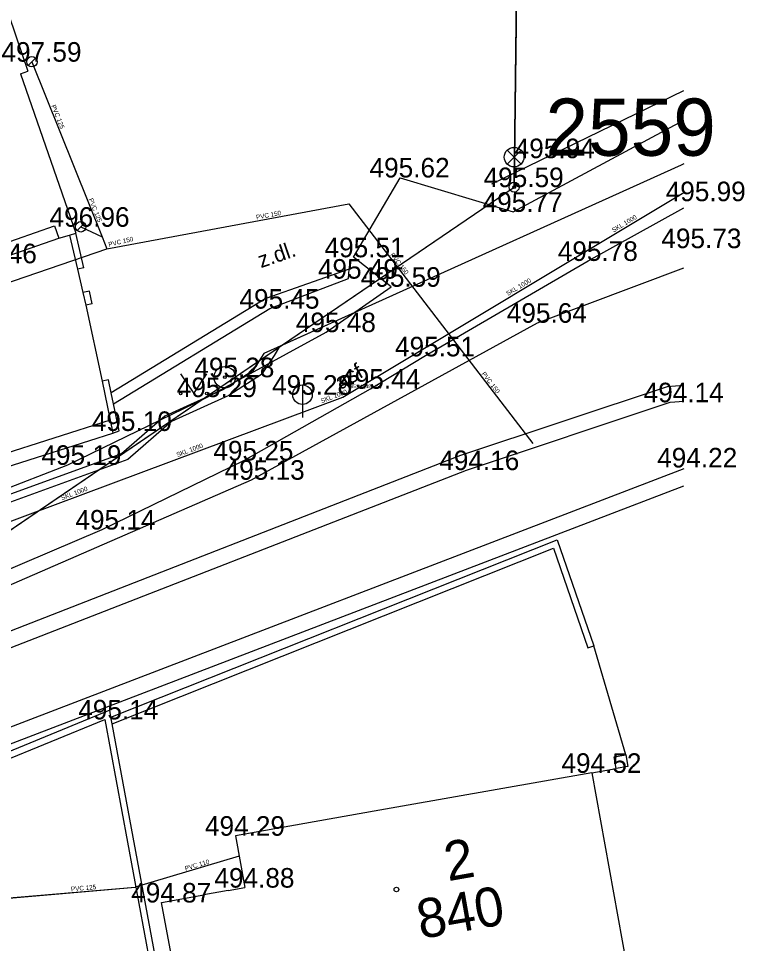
# Model space of a CAD drawing. Extents: x -669642 to -669119, y -1131006 to -1130466.
# Drawn here: x -669215.58 to -669187.76, y -1130590.75 to -1130555.28 of the extents above; entities that cross this region are included whole.
import ezdxf

# ---------------------------------------------------------------- set-up
doc = ezdxf.new("R2010")
doc.units = 0
for name, color, linetype in [('G_Bod_tecka', 7, 'Continuous'), ('G_Bod_vyska', 7, 'Continuous'), ('G_Bodove_pole', 7, 'Continuous'), ('G_Budovy-znacky', 7, 'Continuous'), ('G_Budovy_Objekty', 7, 'Continuous'), ('G_Budovy_vstupy', 7, 'Continuous'), ('G_Cesty_Schody', 7, 'Continuous'), ('G_Cisla_orientacni', 7, 'Continuous'), ('G_Cisla_popisna', 7, 'Continuous'), ('G_Objekty_technicke', 7, 'Continuous'), ('G_Plochy_zpevnene', 7, 'Continuous'), ('G_Ploty', 7, 'Continuous'), ('G_Ploty_vstupy', 7, 'Continuous'), ('G_Popisy_povrchu', 7, 'Continuous'), ('G_Site-kanalizace', 7, 'Continuous'), ('G_Z_ELsilove_podz_kotovane', 7, 'Continuous'), ('G_Z_KANAL_podz_kotovane', 7, 'Continuous'), ('G_Z_KANAL_podz_priblizne', 7, 'Continuous'), ('G_Z_SPOJE_podz_kotovane', 7, 'Continuous'), ('G_Zabradli_Svodidla', 7, 'Continuous'), ('G_Zelen-Znacky', 7, 'Continuous'), ('Vrstva 1', 7, 'Continuous'), ('Vrstva 12', 7, 'Continuous'), ('Vrstva 17', 7, 'Continuous'), ('Vrstva 2', 7, 'Continuous'), ('Vrstva 3', 7, 'Continuous'), ('Vrstva 4', 7, 'Continuous'), ('Vrstva 62', 7, 'Continuous'), ('Vrstva 8', 7, 'Continuous'), ('Vrstva 9', 7, 'Continuous')]:
    doc.layers.add(name, color=color, linetype=linetype)

msp = doc.modelspace()

# ---------------------------------------------------------------- linework, layer by layer
at = {"layer": 'G_Bod_tecka'}
for p, q in [((-669215.07, -1130556.94), (-669215.07, -1130556.94)), ((-669195.41, -1130560.64), (-669195.41, -1130560.64)), ((-669200.96, -1130561.38), (-669200.96, -1130561.38)), ((-669196.59, -1130561.75), (-669196.59, -1130561.75)), ((-669196.63, -1130562.7), (-669196.63, -1130562.7)), ((-669213.2, -1130563.27), (-669213.2, -1130563.27)), ((-669202.75, -1130564.44), (-669202.75, -1130564.44)), ((-669193.75, -1130564.58), (-669193.75, -1130564.58)), ((-669202.94, -1130565.26), (-669202.94, -1130565.26)), ((-669201.3, -1130565.57), (-669201.3, -1130565.57)), ((-669205.95, -1130566.41), (-669205.95, -1130566.41)), ((-669195.69, -1130566.95), (-669195.69, -1130566.95)), ((-669203.79, -1130567.31), (-669203.79, -1130567.31)), ((-669200.05, -1130568.24), (-669200.05, -1130568.24)), ((-669207.68, -1130569.04), (-669207.68, -1130569.04)), ((-669202.09, -1130569.48), (-669202.09, -1130569.48)), ((-669208.35, -1130569.8), (-669208.35, -1130569.8)), ((-669204.7, -1130569.71), (-669204.7, -1130569.71)), ((-669190.61, -1130570), (-669190.61, -1130570)), ((-669211.73, -1130571.1), (-669211.73, -1130571.1)), ((-669213.69, -1130572.4), (-669213.69, -1130572.4)), ((-669206.95, -1130572.23), (-669206.95, -1130572.23)), ((-669198.42, -1130572.6), (-669198.42, -1130572.6)), ((-669206.66, -1130572.97), (-669206.66, -1130572.97)), ((-669212.38, -1130574.88), (-669212.38, -1130574.88)), ((-669212.28, -1130582.16), (-669212.28, -1130582.16)), ((-669193.61, -1130584.21), (-669193.61, -1130584.21)), ((-669207.27, -1130586.62), (-669207.27, -1130586.62)), ((-669206.91, -1130588.61), (-669206.91, -1130588.61)), ((-669210.1, -1130589.18), (-669210.1, -1130589.18))]:
    msp.add_line(p, q, dxfattribs=at)
at = {"layer": 'G_Bodove_pole'}
for radius in [0.412, 0.05]:
    msp.add_circle((-669207.68, -1130569.04), radius, dxfattribs=at)
at = {"layer": 'G_Budovy-znacky'}
msp.add_circle((-669201.1, -1130588.681), 0.0875, dxfattribs=at)
at = {"layer": 'G_Budovy_Objekty'}
for p, q in [((-669216.92, -1130552.29), (-669215.23, -1130557.3)), ((-669215.51, -1130557.4), (-669215.23, -1130557.3)), ((-669215.51, -1130557.4), (-669213.39, -1130563.52)), ((-669214.21, -1130563.24), (-669214.04, -1130563.71)), ((-669214.04, -1130563.71), (-669213.63, -1130563.59)), ((-669213.63, -1130563.59), (-669213.39, -1130563.52)), ((-669216.27, -1130564.49), (-669214.04, -1130563.71)), ((-669193.61, -1130584.21), (-669200.87, -1130585.49)), ((-669193.61, -1130584.21), (-669192.25, -1130591.72)), ((-669201.95, -1130585.68), (-669207.27, -1130586.62)), ((-669207.27, -1130586.62), (-669206.91, -1130588.61)), ((-669207.55, -1130588.72), (-669206.91, -1130588.61)), ((-669210.1, -1130589.18), (-669208.48, -1130588.89)), ((-669209.1, -1130594.59), (-669210.1, -1130589.18))]:
    msp.add_line(p, q, dxfattribs=at)
at = {"layer": 'G_Budovy_vstupy'}
for p, q in [((-669216.44, -1130564.02), (-669214.21, -1130563.24)), ((-669200.87, -1130585.49), (-669201.95, -1130585.68)), ((-669207.55, -1130588.72), (-669208.48, -1130588.89))]:
    msp.add_line(p, q, dxfattribs=at)
at = {"layer": 'G_Cesty_Schody'}
msp.add_line((-669197.45, -1130561.63), (-669190.087, -1130558.049), dxfattribs=at)
at = {"layer": 'G_Objekty_technicke'}
for p, q in [((-669196.855, -1130560.335), (-669196.325, -1130560.865)), ((-669196.855, -1130560.865), (-669196.325, -1130560.335)), ((-669196.59, -1130561.75), (-669196.59, -1130560.975))]:
    msp.add_line(p, q, dxfattribs=at)
for centre, radius in [((-669196.59, -1130560.6), 0.375), ((-669196.59, -1130561.75), 0.19), ((-669196.59, -1130561.75), 0.05)]:
    msp.add_circle(centre, radius, dxfattribs=at)
at = {"layer": 'G_Plochy_zpevnene'}
for p, q in [((-669196.63, -1130562.7), (-669190.087, -1130559.182)), ((-669200.05, -1130568.24), (-669193.75, -1130564.58)), ((-669202.91, -1130564.9), (-669206.1, -1130566.02)), ((-669206.1, -1130566.02), (-669212.03, -1130569.64)), ((-669211.94, -1130570.06), (-669205.95, -1130566.41)), ((-669208.35, -1130569.8), (-669203.79, -1130567.31)), ((-669202.09, -1130569.48), (-669200.05, -1130568.24)), ((-669206.95, -1130572.23), (-669202.09, -1130569.48)), ((-669190.73, -1130569.41), (-669198.64, -1130572.04)), ((-669190.087, -1130569.352), (-669190.73, -1130569.41)), ((-669213.69, -1130572.4), (-669208.35, -1130569.8)), ((-669198.42, -1130572.6), (-669190.61, -1130570)), ((-669190.61, -1130570), (-669190.087, -1130569.953)), ((-669212.07, -1130570.68), (-669222.72, -1130574.08)), ((-669222.56, -1130574.56), (-669211.97, -1130571.18)), ((-669211.97, -1130571.18), (-669211.73, -1130571.1)), ((-669198.64, -1130572.04), (-669224.85, -1130582.26)), ((-669220.59, -1130575.08), (-669213.69, -1130572.4)), ((-669212.38, -1130574.88), (-669206.95, -1130572.23)), ((-669224.63, -1130582.82), (-669198.42, -1130572.6)), ((-669190.087, -1130572.557), (-669224.48, -1130585.75)), ((-669224.28, -1130586.31), (-669190.087, -1130573.2)), ((-669219.68, -1130577.99), (-669212.38, -1130574.88))]:
    msp.add_line(p, q, dxfattribs=at)
for points in [[(-669203.79, -1130567.31), (-669201.3, -1130565.57), (-669202.75, -1130564.44), (-669200.96, -1130561.39), (-669196.63, -1130562.7)], [(-669193.75, -1130564.58), (-669190.087, -1130562.549)], [(-669205.95, -1130566.41), (-669202.94, -1130565.26), (-669202.91, -1130564.9)]]:
    msp.add_lwpolyline(points, dxfattribs=at)
at = {"layer": 'G_Ploty'}
for p, q in [((-669213.63, -1130563.59), (-669213.32, -1130564.9)), ((-669213.08, -1130564.84), (-669213.39, -1130563.52)), ((-669213.08, -1130564.84), (-669213.32, -1130564.9)), ((-669212.87, -1130565.74), (-669213.12, -1130565.79)), ((-669212.76, -1130566.22), (-669212.87, -1130565.74)), ((-669213.12, -1130565.79), (-669213, -1130566.28)), ((-669212.76, -1130566.22), (-669213, -1130566.28)), ((-669212.13, -1130569.14), (-669212.38, -1130569.19)), ((-669212.38, -1130569.19), (-669212.07, -1130570.68)), ((-669212.03, -1130569.64), (-669212.13, -1130569.14)), ((-669211.94, -1130570.06), (-669212.03, -1130569.64)), ((-669211.73, -1130571.1), (-669211.94, -1130570.06)), ((-669212.07, -1130570.68), (-669211.97, -1130571.18)), ((-669212.04, -1130582.07), (-669194.94, -1130575.28)), ((-669194.94, -1130575.28), (-669193.53, -1130579.34)), ((-669211.99, -1130582.33), (-669195.08, -1130575.6)), ((-669212.08, -1130581.81), (-669225.52, -1130587.34)), ((-669212.04, -1130582.07), (-669212.08, -1130581.81)), ((-669225.42, -1130587.57), (-669212.28, -1130582.16)), ((-669212.28, -1130582.16), (-669209.73, -1130595.91)), ((-669211.99, -1130582.33), (-669212.04, -1130582.07)), ((-669209.71, -1130594.68), (-669211.99, -1130582.33)), ((-669192.76, -1130583.6), (-669192.31, -1130583.52)), ((-669192.68, -1130584.04), (-669192.76, -1130583.6)), ((-669192.31, -1130583.52), (-669192.23, -1130583.96)), ((-669192.23, -1130583.96), (-669192.68, -1130584.04))]:
    msp.add_line(p, q, dxfattribs=at)
msp.add_lwpolyline([(-669195.08, -1130575.6), (-669193.77, -1130579.42), (-669193.53, -1130579.34)], dxfattribs=at)
at = {"layer": 'G_Ploty_vstupy'}
for p, q in [((-669213.32, -1130564.9), (-669213.12, -1130565.79)), ((-669213, -1130566.28), (-669212.38, -1130569.19)), ((-669192.31, -1130583.52), (-669193.53, -1130579.34)), ((-669193.61, -1130584.21), (-669192.68, -1130584.04))]:
    msp.add_line(p, q, dxfattribs=at)
at = {"layer": 'G_Site-kanalizace'}
msp.add_line((-669204.7, -1130569.335), (-669204.7, -1130570.585), dxfattribs=at)
for points in [[(-669214.929, -1130556.799), (-669215.07, -1130556.94), (-669215.212, -1130557.082)], [(-669213.059, -1130563.129), (-669213.2, -1130563.27), (-669213.342, -1130563.412)]]:
    msp.add_lwpolyline(points, dxfattribs=at)
for centre, radius in [((-669215.07, -1130556.941), 0.2), ((-669213.2, -1130563.271), 0.2), ((-669204.7, -1130569.71), 0.375)]:
    msp.add_circle(centre, radius, dxfattribs=at)
at = {"layer": 'G_Z_ELsilove_podz_kotovane'}
for points in [[(-669335.66, -1130601.68), (-669301.36, -1130595.66), (-669264.19, -1130588.13), (-669223.67, -1130580.18), (-669196.59, -1130561.75), (-669196.42, -1130548.14)], [(-669190.087, -1130560.862), (-669190.185, -1130560.912), (-669202.7, -1130566.561), (-669206.188, -1130568.135)], [(-669206.188, -1130568.135), (-669206.61, -1130568.79), (-669207.75, -1130569.52), (-669209.98, -1130570.53), (-669211.64, -1130571.98), (-669216.03, -1130573.57)]]:
    msp.add_lwpolyline(points, dxfattribs=at)
at = {"layer": 'G_Z_KANAL_podz_kotovane'}
for p, q in [((-669246.97, -1130586.18), (-669203.16, -1130569.81)), ((-669207.13, -1130587.41), (-669211.12, -1130588.59)), ((-669225.84, -1130589.86), (-669211.12, -1130588.59))]:
    msp.add_line(p, q, dxfattribs=at)
msp.add_lwpolyline([(-669203.16, -1130569.81), (-669190.15, -1130562), (-669190.087, -1130561.974)], dxfattribs=at)
at = {"layer": 'G_Z_KANAL_podz_priblizne'}
msp.add_line((-669213.2, -1130563.27), (-669212.38, -1130563.65), dxfattribs=at)
for points in [[(-669215.07, -1130556.94), (-669212.38, -1130563.65), (-669212.2, -1130564.11)], [(-669226.24, -1130565.86), (-669222.01, -1130567.48), (-669212.2, -1130564.11), (-669202.92, -1130562.39), (-669195.87, -1130571.58)]]:
    msp.add_lwpolyline(points, dxfattribs=at)
at = {"layer": 'G_Z_SPOJE_podz_kotovane'}
for points in [[(-669190.087, -1130560.862), (-669190.185, -1130560.912), (-669202.7, -1130566.561), (-669205.582, -1130567.856), (-669205.79, -1130568.201)], [(-669190.087, -1130560.862), (-669190.185, -1130560.912), (-669202.7, -1130566.561), (-669205.582, -1130567.856), (-669205.79, -1130568.201)], [(-669205.79, -1130568.201), (-669206.266, -1130568.938), (-669207.522, -1130569.743), (-669209.719, -1130570.738), (-669211.394, -1130572.2), (-669215.891, -1130573.829)], [(-669205.79, -1130568.201), (-669206.266, -1130568.938), (-669207.522, -1130569.743), (-669209.719, -1130570.738), (-669211.394, -1130572.2), (-669215.891, -1130573.829)]]:
    msp.add_lwpolyline(points, dxfattribs=at)
at = {"layer": 'G_Zabradli_Svodidla'}
for p, q in [((-669195.69, -1130566.95), (-669190.087, -1130564.851)), ((-669206.66, -1130572.97), (-669195.69, -1130566.95))]:
    msp.add_line(p, q, dxfattribs=at)
msp.add_lwpolyline([(-669228.15, -1130583.58), (-669224.97, -1130582.2), (-669225.24, -1130581.07), (-669206.66, -1130572.97)], dxfattribs=at)
at = {"layer": 'G_Zelen-Znacky'}
for p, q in [((-669209.37, -1130568.91), (-669208.87, -1130569.66)), ((-669208.87, -1130569.66), (-669208.37, -1130568.91))]:
    msp.add_line(p, q, dxfattribs=at)
for centre in [(-669209.37, -1130569.66), (-669208.37, -1130569.66)]:
    msp.add_circle(centre, 0.05, dxfattribs=at)
at = {"layer": 'Vrstva 1'}
msp.add_line((-669196.59, -1130561.75), (-669196.59, -1130561.75), dxfattribs=at)
at = {"layer": 'Vrstva 12'}
for p, q in [((-669246.97, -1130586.18), (-669203.16, -1130569.81)), ((-669207.127, -1130587.41), (-669211.12, -1130588.594)), ((-669225.835, -1130589.86), (-669211.12, -1130588.594))]:
    msp.add_line(p, q, dxfattribs=at)
msp.add_lwpolyline([(-669203.16, -1130569.81), (-669190.15, -1130562), (-669190.087, -1130561.974)], dxfattribs=at)
at = {"layer": 'Vrstva 17'}
msp.add_line((-669196.42, -1130548.14), (-669196.59, -1130561.75), dxfattribs=at)
at = {"layer": 'Vrstva 62'}
msp.add_line((-669223.67, -1130580.18), (-669196.59, -1130561.75), dxfattribs=at)
at = {"layer": 'Vrstva 8'}
msp.add_line((-669203.16, -1130569.81), (-669203.16, -1130569.81), dxfattribs=at)
at = {"layer": 'Vrstva 9'}
msp.add_line((-669213.2, -1130563.27), (-669212.38, -1130563.65), dxfattribs=at)
for points in [[(-669215.07, -1130556.94), (-669212.38, -1130563.65), (-669212.2, -1130564.11)], [(-669226.24, -1130565.86), (-669222.01, -1130567.48), (-669212.2, -1130564.11), (-669202.92, -1130562.39), (-669195.87, -1130571.58)]]:
    msp.add_lwpolyline(points, dxfattribs=at)

# ---------------------------------------------------------------- texts
at = {"layer": 'G_Bod_vyska'}
for s, p in [('497.59', (-669216.238, -1130556.94)), ('495.94', (-669196.568, -1130560.64)), ('495.62', (-669202.13, -1130561.38)), ('495.59', (-669197.758, -1130561.75)), ('495.99', (-669190.78, -1130562.29)), ('495.77', (-669197.796, -1130562.7)), ('496.96', (-669214.395, -1130563.27)), ('495.73', (-669190.946, -1130564.09)), ('497.46', (-669217.95, -1130564.67)), ('495.51', (-669203.854, -1130564.44)), ('495.78', (-669194.916, -1130564.58)), ('495.49', (-669204.108, -1130565.26)), ('495.59', (-669202.468, -1130565.57)), ('495.45', (-669207.116, -1130566.41)), ('495.64', (-669196.87, -1130566.95)), ('495.48', (-669204.956, -1130567.31)), ('495.51', (-669201.154, -1130568.24)), ('495.28', (-669208.846, -1130569.04)), ('495.44', (-669203.256, -1130569.48)), ('495.29', (-669209.518, -1130569.8)), ('495.28', (-669205.866, -1130569.71)), ('494.14', (-669191.624, -1130570)), ('495.10', (-669212.776, -1130571.1)), ('495.19', (-669214.706, -1130572.4)), ('495.25', (-669208.116, -1130572.23)), ('494.22', (-669191.106, -1130572.5)), ('494.16', (-669199.458, -1130572.6)), ('495.13', (-669207.684, -1130572.97)), ('495.14', (-669213.404, -1130574.88)), ('495.14', (-669213.294, -1130582.16)), ('494.52', (-669194.776, -1130584.21)), ('494.29', (-669208.438, -1130586.62)), ('494.88', (-669208.076, -1130588.61)), ('494.87', (-669211.266, -1130589.18))]:
    msp.add_text(s, height=0.75, dxfattribs=at).set_placement(p)
at = {"layer": 'G_Cisla_orientacni'}
msp.add_text('2', height=1.5, rotation=10.0656, dxfattribs=at).set_placement((-669199.123, -1130588.368))
at = {"layer": 'G_Cisla_popisna'}
msp.add_text('840', height=1.5, rotation=10.0656, dxfattribs=at).set_placement((-669200.172, -1130590.584))
at = {"layer": 'G_Popisy_povrchu'}
for s, rotation, p in [('z.dl.', 18.9626, (-669206.292, -1130564.86)), ('asf.', 30.0897, (-669203.243, -1130569.537))]:
    msp.add_text(s, height=0.6, rotation=rotation, dxfattribs=at).set_placement(p)
at = {"layer": 'Vrstva 2'}
msp.add_text('495.31 (492.68)', height=0.13163, dxfattribs=at).set_placement((-669202.954, -1130569.457))
at = {"layer": 'Vrstva 3'}
for s, rotation, p in [('PVC 125', 291.8456, (-669214.335, -1130558.632)), ('PVC 125', 291.8456, (-669212.901, -1130562.217)), ('PVC 150', 10.4797, (-669206.462, -1130562.993)), ('SKL 1000', 30.969, (-669192.779, -1130563.495)), ('PVC 150', 13.2025, (-669212.116, -1130564.036)), ('PVC 150', 307.4109, (-669201.348, -1130564.353)), ('SKL 1000', 31.0002, (-669196.827, -1130565.926)), ('PVC 150', 307.4649, (-669197.849, -1130568.913)), ('SKL 1000', 20.5098, (-669203.967, -1130570.036)), ('SKL 1000', 20.5098, (-669209.495, -1130572.102)), ('SKL 1000', 20.4992, (-669213.918, -1130573.755)), ('PVC 110', 16.4941, (-669209.182, -1130587.965)), ('PVC 125', 4.9388, (-669213.567, -1130588.752))]:
    msp.add_text(s, height=0.1755, rotation=rotation, dxfattribs=at).set_placement(p)
at = {"layer": 'Vrstva 4'}
msp.add_text('2559', height=2.1939, dxfattribs=at).set_placement((-669195.386, -1130560.548))

doc.saveas('drawing.dxf')
